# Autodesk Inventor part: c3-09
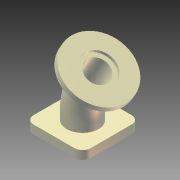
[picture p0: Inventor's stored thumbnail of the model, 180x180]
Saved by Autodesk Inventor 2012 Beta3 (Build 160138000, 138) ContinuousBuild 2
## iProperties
Created: 2010-11
Part Number: c3-09
Material: Cast Iron
Document SubType Name: Modeling
Designer: Beta-8540w
Density: 7.25 g/cm^3
Mass: 1087.5 g
Surface Area: 260 cm^2
Volume: 150 cm^3
Author: Beta-8540w
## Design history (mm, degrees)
sketch "Sketch1"
  geometry: L1 (-50, -50)-(50, -50); L2 (50, -50)-(50, 50); L3 (50, 50)-(-50, 50); L4 (-50, 50)-(-50, -50); C1 r 20 at (0, 0); C2 r 28 at (0, 0); 3 further points
  constraints: 8 end point, 3 perpendicular, 2 centre point, 2 coincident, 2 midpoint, 1 horizontal, 1 horizontal alignment, 1 parallel, 1 vertical alignment
  dimensions: "Width" = 100 distance of L1.start L1.end; "d6" = 40 diameter of C1; "d7" = 8 radial gap between concentric circles of C2 C1
extrude "Extrusion1" new body sketch "Sketch1" distance "d3" = 15; taper "d4" = 0 deg
fillet "Fillet1" dims "d5" = 14
sketch "Sketch2"
  geometry: L1 (0, 0)-(0, 30); L2 (-13.397, 80)-(-28.397, 105.981); A1 r 100 centre (-100, 30) between (0, 30) and (-13.397, 80)
  constraints: 4 end point, 2 point on circle, 2 tangent, 1 centre point, 1 vertical
  dimensions: "d8" = 30 distance of L1.start L1.end; "d9" = 100 radius of A1; "d10" = 30 distance of L2.start L2.end; "d11" = 30 deg angle of L2 L1
sketch "Sketch3"
  geometry: L1 (-13.397, 80)-(-28.397, 105.981) reference; L2 (-28.397, 105.981)-(-76.029, 78.481); L3 (-76.029, 78.481)-(-71.029, 69.821); L4 (-71.029, 69.821)-(-23.397, 97.321); L5 (-23.397, 97.321)-(-28.397, 105.981); 1 further point
  constraints: 8 end point, 2 parallel, 2 perpendicular
  dimensions: "d16" = 10 distance of L3.end L2.end; "d17" = 110 diameter of L3 L5
revolve "Revolution1" sketch "Sketch3" stored, may be unused: angle "d18" = 90 deg
sweep "Sweep1" dims "d19" = 0
sweep "Sweep2" dims "d20" = 0
sketch "Sketch4"
  geometry: C1 r 20 at (0, 0) reference; C2 r 55 at (0, 0) reference; C3 r 27.5 at (0, 0); 1 further point
  constraints: 1 centre point, 1 coincident
  dimensions: "d21" = 55 diameter of C3
extrude "Extrusion2" cut sketch "Sketch4" distance "d22" = 5; taper "d23" = 0 deg
sketch "Sketch5"
  geometry: L1 (0, 0)-(0, 9.711); L2 (-25, 0)-(-27, 0); L3 (-27, 0)-(-27, 1.5); L4 (-26.5, 2)-(-25.5, 2); L5 (-25, 1.5)-(-25, 0); A1 r 0.5 centre (-25.5, 1.5) between (-25, 1.5) and (-25.5, 2); A2 r 0.5 centre (-26.5, 1.5) between (-26.5, 2) and (-27, 1.5); 1 further point
  constraints: 10 end point, 4 point on circle, 4 tangent, 3 point on line, 2 centre point, 2 parallel, 1 equal radius, 1 horizontal, 1 perpendicular, 1 vertical
  dimensions: "d24" = 2 distance of L2.start L2.end; "d25" = 2 distance of point (-25, 2) L2.start; "d26" = 50 diameter of L5 L1; "d27" = 0.5 radius of A1
revolve "Revolution2" sketch "Sketch5" stored, may be unused: angle "d28" = 90 deg
body "Solid1"
